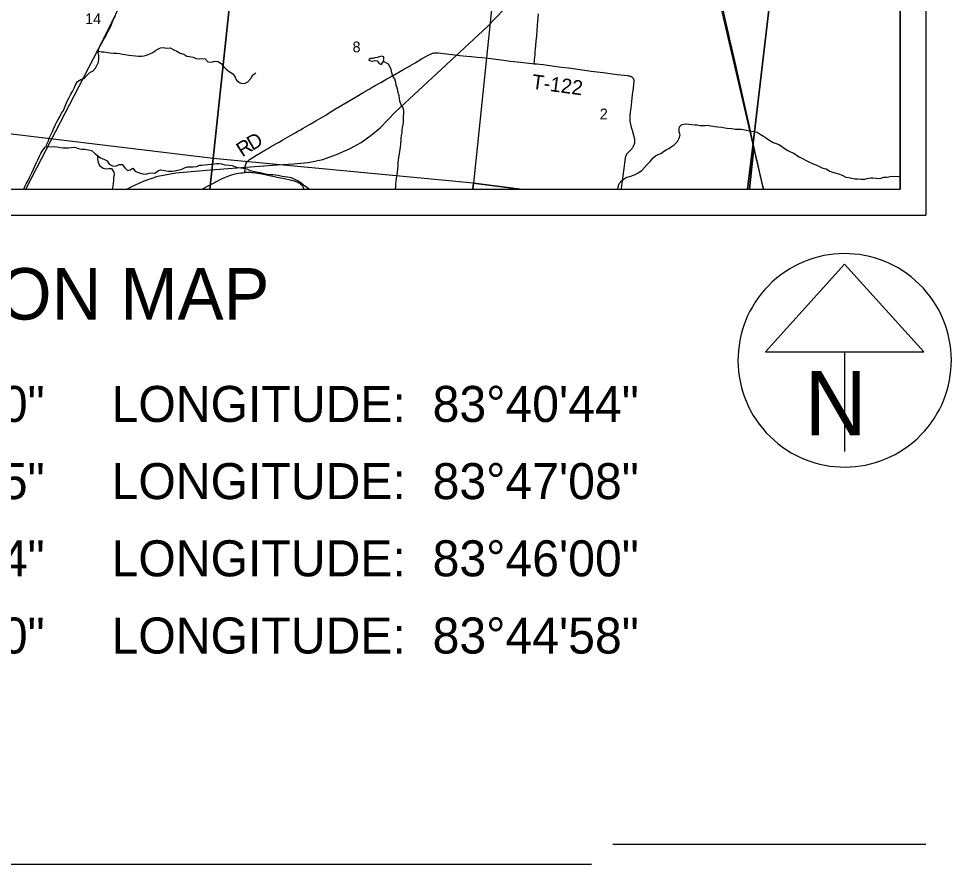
# Model space of a CAD drawing. Extents: x 831 to 1552, y 430 to 870.
# Drawn here: x 1013.2 to 1085.8, y 598.5 to 664.2 of the extents above; entities that cross this region are included whole.
import ezdxf

# ---------------------------------------------------------------- set-up
doc = ezdxf.new("R2010")
doc.units = 0
for name, color, linetype in [('GM_X_Corporation', 7, 'Continuous'), ('GM_X_Minor_Lake', 7, 'Continuous'), ('GM_X_Minor_River', 7, 'Continuous'), ('GM_X_Rail_Line', 7, 'Continuous'), ('GM_X_Section_Text', 7, 'Continuous'), ('GM_X_State_Route', 7, 'Continuous'), ('GM_X_Township_Road', 7, 'Continuous'), ('GM_X_Township_Road_Text', 7, 'Continuous'), ('SH_Data', 7, 'Continuous'), ('SH_Text', 7, 'Continuous')]:
    doc.layers.add(name, color=color, linetype=linetype)

msp = doc.modelspace()

# ---------------------------------------------------------------- linework, layer by layer
at = {"layer": 'GM_X_Corporation'}
msp.add_lwpolyline([(957.479, 781.045), (956.56, 771.006), (955.451, 760.717), (953.653, 740.871), (952.689, 730.885), (949.971, 703.401), (947.763, 681.071), (945.766, 658.183), (945.766, 650.938), (1069.909, 650.938), (1070.34, 654.531), (1072.813, 675.454), (1078.126, 715.958), (1081.227, 740.59), (1081.766, 744.853), (1081.766, 786.938)], dxfattribs=at)
for points in [[(1069.909, 650.938), (1081.766, 650.938), (1081.766, 744.853), (1081.227, 740.59), (1078.126, 715.958), (1072.813, 675.454), (1070.34, 654.531)], [(1030.47, 673.244), (1028.346, 653.321), (1007.707, 655.818), (1009.676, 675.38)], [(1030.47, 673.244), (1050.619, 670.912), (1048.583, 651.419), (1028.346, 653.321)], [(1052.227, 650.938), (1070.052, 650.938), (1070.404, 654.192), (1066.955, 668.986), (1050.619, 670.912), (1048.583, 651.419)], [(1007.28, 650.938), (1028.103, 650.938), (1028.346, 653.321), (1007.707, 655.818)], [(1070.052, 650.938), (1071.14, 650.938), (1070.404, 654.192)], [(1028.103, 650.938), (1048.532, 650.938), (1048.583, 651.419), (1028.346, 653.321)], [(1048.532, 650.938), (1052.227, 650.938), (1048.583, 651.419)]]:
    msp.add_lwpolyline(points, close=True, dxfattribs=at)
at = {"layer": 'GM_X_Minor_Lake'}
for points in [[(1040.485, 661.031), (1040.429, 660.991), (1040.58, 660.92), (1040.77, 660.895), (1040.945, 660.946), (1041.097, 660.913), (1041.246, 660.721), (1041.411, 660.628), (1041.597, 660.868)], [(1041.597, 660.868), (1041.615, 661.05), (1041.617, 661.225), (1041.436, 661.273), (1041.268, 661.222), (1041.093, 661.179), (1040.925, 661.159), (1040.765, 661.115), (1040.583, 661.103), (1040.485, 661.031)]]:
    msp.add_lwpolyline(points, dxfattribs=at)
at = {"layer": 'GM_X_Minor_River'}
for points in [[(1015.364, 654.238), (1015.408, 654.452), (1015.533, 654.716), (1015.604, 654.921), (1015.737, 655.162), (1015.847, 655.442), (1015.95, 655.698), (1016.067, 655.932), (1016.161, 656.136), (1016.293, 656.355), (1016.418, 656.558), (1016.566, 656.852), (1016.706, 657.056), (1016.792, 657.275), (1016.887, 657.539), (1016.989, 657.781), (1017.145, 658.075), (1017.262, 658.279), (1017.426, 658.588), (1017.535, 658.792), (1017.645, 659.048), (1017.808, 659.312), (1018.069, 659.483), (1018.313, 659.541), (1018.552, 659.811), (1018.798, 660.051), (1018.989, 660.116), (1019.19, 660.357), (1019.338, 660.621), (1019.432, 660.817), (1019.466, 661.075), (1019.447, 661.341), (1019.397, 661.569), (1019.454, 661.857), (1019.533, 662.054), (1019.681, 662.295), (1019.798, 662.521), (1019.945, 662.747), (1020.063, 662.981), (1020.188, 663.238), (1020.305, 663.471), (1020.446, 663.758), (1020.532, 663.962), (1020.611, 664.159), (1020.752, 664.43)], [(1019.418, 661.674), (1019.671, 661.634), (1019.876, 661.616), (1020.164, 661.567), (1020.369, 661.541), (1020.604, 661.53), (1020.854, 661.527), (1021.074, 661.493), (1021.309, 661.452), (1021.513, 661.404), (1021.786, 661.355), (1022.059, 661.336), (1022.309, 661.302), (1022.544, 661.276), (1022.757, 661.281), (1022.985, 661.3), (1023.176, 661.374), (1023.42, 661.469), (1023.665, 661.58), (1023.856, 661.714), (1024.055, 661.817), (1024.247, 661.929), (1024.46, 661.971), (1024.732, 661.899), (1024.999, 661.941), (1025.3, 661.77), (1025.526, 661.668), (1025.775, 661.52), (1026.07, 661.448), (1026.31, 661.285), (1026.507, 661.252), (1026.803, 661.195), (1027.006, 661.101), (1027.249, 661.082), (1027.515, 661.094), (1027.727, 661.076), (1027.944, 660.837), (1028.202, 660.826), (1028.469, 660.906), (1028.734, 660.872), (1028.998, 660.686), (1029.154, 660.486), (1029.386, 660.248), (1029.672, 660.046), (1029.875, 659.899), (1030.053, 659.646), (1030.164, 659.432), (1030.389, 659.231), (1030.586, 659.16), (1030.836, 659.179), (1031.051, 659.298), (1031.267, 659.546), (1031.423, 659.825), (1031.676, 659.988)], [(1042.533, 650.938), (1042.544, 651.132), (1042.555, 651.337), (1042.58, 651.541), (1042.614, 651.754), (1042.64, 651.974), (1042.674, 652.231), (1042.708, 652.527), (1042.727, 652.762), (1042.745, 652.982), (1042.763, 653.187), (1042.79, 653.438), (1042.831, 653.68), (1042.872, 653.892), (1042.907, 654.196), (1042.949, 654.491), (1042.96, 654.727), (1042.97, 654.924), (1042.996, 655.129), (1043.037, 655.356), (1043.055, 655.546), (1043.081, 655.743), (1043.114, 655.963), (1043.14, 656.167), (1043.158, 656.41), (1043.161, 656.6), (1043.172, 656.82), (1043.175, 657.071), (1043.095, 657.315), (1042.969, 657.507), (1042.874, 657.781), (1042.832, 658.002), (1042.804, 658.193), (1042.74, 658.459), (1042.675, 658.734), (1042.588, 659.031), (1042.561, 659.229), (1042.466, 659.527), (1042.332, 659.726), (1042.245, 660.001), (1042.18, 660.245), (1042.115, 660.436), (1041.974, 660.673), (1041.597, 660.868)], [(1059.81, 650.938), (1059.84, 651.126), (1059.919, 651.39), (1060.128, 651.623), (1060.419, 651.816), (1060.633, 651.904), (1060.824, 651.962), (1061.175, 652.094), (1061.412, 652.227), (1061.68, 652.405), (1061.904, 652.63), (1062.097, 652.855), (1062.328, 653.11), (1062.567, 653.395), (1062.759, 653.544), (1062.966, 653.633), (1063.157, 653.728), (1063.364, 653.885), (1063.571, 653.996), (1063.777, 654.099), (1063.969, 654.233), (1064.206, 654.382), (1064.453, 654.659), (1064.586, 654.908), (1064.673, 655.173), (1064.6, 655.402), (1064.588, 655.592), (1064.606, 655.781), (1064.806, 655.984), (1065.11, 656.025), (1065.376, 656.006), (1065.573, 655.965), (1065.793, 655.947), (1065.99, 655.944), (1066.217, 655.902), (1066.407, 655.885), (1066.597, 655.897), (1066.802, 655.909), (1067.06, 655.875), (1067.37, 655.818), (1067.597, 655.784), (1067.908, 655.757), (1068.135, 655.715), (1068.325, 655.69), (1068.689, 655.654), (1068.954, 655.62), (1069.159, 655.61), (1069.432, 655.606), (1069.697, 655.557), (1069.962, 655.5), (1070.159, 655.459), (1070.424, 655.44), (1070.651, 655.368), (1070.877, 655.228), (1071.133, 655.065), (1071.366, 654.902), (1071.629, 654.724), (1071.9, 654.568), (1072.119, 654.489), (1072.331, 654.41), (1072.541, 654.293), (1072.759, 654.138), (1073.045, 653.952), (1073.294, 653.835), (1073.513, 653.74), (1073.708, 653.586), (1073.927, 653.469), (1074.183, 653.344), (1074.469, 653.165), (1074.725, 653.04), (1074.967, 652.93), (1075.261, 652.82), (1075.495, 652.718), (1075.759, 652.585), (1076.016, 652.521), (1076.31, 652.357), (1076.521, 652.263), (1076.786, 652.183), (1076.99, 652.135), (1077.255, 652.032), (1077.556, 651.884)], [(1013.62, 650.938), (1013.713, 651.148), (1013.815, 651.359), (1013.955, 651.631), (1014.073, 651.865), (1014.182, 652.068), (1014.268, 652.272), (1014.37, 652.491), (1014.48, 652.748), (1014.582, 652.959), (1014.707, 653.216), (1014.856, 653.518), (1014.942, 653.714), (1015.098, 653.985), (1015.306, 654.233), (1015.549, 654.253), (1015.762, 654.227), (1016.035, 654.261), (1016.225, 654.244), (1016.475, 654.195), (1016.679, 654.154), (1016.869, 654.159)], [(1016.869, 654.159), (1017.112, 654.171), (1017.318, 654.183), (1017.591, 654.202), (1017.863, 654.1), (1018.121, 654.058), (1018.356, 654.063), (1018.644, 654.006), (1018.894, 653.949), (1019.126, 653.748), (1019.351, 653.555), (1019.599, 653.377), (1019.841, 653.267), (1020.105, 653.158), (1020.261, 652.889), (1020.525, 652.772), (1020.79, 652.723), (1021.042, 652.856), (1021.285, 652.86), (1021.479, 652.599), (1021.696, 652.391), (1021.902, 652.457), (1022.093, 652.568), (1022.288, 652.345), (1022.59, 652.22), (1022.869, 652.14), (1023.097, 652.114), (1023.379, 652.194), (1023.637, 652.205), (1023.827, 652.195), (1024.088, 652.397), (1024.279, 652.447), (1024.574, 652.398), (1024.839, 652.341), (1025.158, 652.344), (1025.348, 652.364), (1025.592, 652.429), (1025.866, 652.486), (1026.126, 652.597), (1026.362, 652.677), (1026.59, 652.689), (1026.803, 652.671), (1027.084, 652.72), (1027.275, 652.801), (1027.481, 652.814), (1027.671, 652.834), (1027.945, 652.876), (1028.226, 652.895), (1028.416, 652.907), (1028.606, 652.935), (1028.796, 652.94), (1029.001, 652.914), (1029.265, 652.85), (1029.599, 652.8), (1029.819, 652.782), (1030.098, 652.671), (1030.303, 652.631), (1030.5, 652.605), (1030.689, 652.58), (1030.962, 652.523), (1031.226, 652.405), (1031.423, 652.357), (1031.703, 652.3), (1031.998, 652.243), (1032.301, 652.163), (1032.558, 652.121), (1032.808, 652.095), (1032.998, 652.077), (1033.195, 652.052), (1033.407, 652.026), (1033.71, 651.968), (1033.93, 651.92), (1034.134, 651.902), (1034.414, 651.845), (1034.671, 651.727), (1034.965, 651.587), (1035.161, 651.462), (1035.363, 651.285), (1035.634, 651.091), (1035.852, 650.959), (1035.872, 650.938)], [(1019.344, 653.562), (1019.348, 653.305), (1019.405, 653.038), (1019.515, 652.793), (1019.793, 652.577), (1019.997, 652.521), (1020.233, 652.563), (1020.438, 652.545), (1020.624, 652.269), (1020.659, 652.071), (1020.61, 651.836), (1020.6, 651.639), (1020.573, 651.389), (1020.548, 651.191), (1020.507, 650.979), (1020.502, 650.938)], [(1077.556, 651.884), (1077.746, 651.858), (1078.003, 651.802), (1078.245, 651.76), (1078.488, 651.742), (1078.746, 651.723), (1079.019, 651.712), (1079.21, 651.77), (1079.461, 651.82), (1079.651, 651.825), (1079.901, 651.791), (1080.091, 651.766), (1080.296, 651.808), (1080.51, 651.874), (1080.73, 651.886), (1081.004, 651.935), (1081.194, 651.948), (1081.665, 651.941), (1081.766, 651.917)]]:
    msp.add_lwpolyline(points, dxfattribs=at)
at = {"layer": 'GM_X_Rail_Line'}
for points in [[(1013.791, 650.938), (1014.28, 651.895), (1019.767, 662.513), (1021.761, 666.57)], [(1021.639, 650.938), (1022.016, 651.166), (1022.93, 651.563), (1024.049, 651.948), (1025.46, 652.211), (1028.142, 652.462), (1031.589, 652.721), (1033.328, 652.847), (1034.588, 652.912), (1035.748, 653.032), (1036.888, 653.266), (1037.951, 653.654), (1038.992, 654.116), (1039.861, 654.582), (1040.64, 655.139), (1041.328, 655.716), (1042.519, 656.956), (1049.69, 663.597), (1050.96, 664.907)]]:
    msp.add_lwpolyline(points, dxfattribs=at)
at = {"layer": 'GM_X_State_Route'}
for points in [[(1070.344, 654.52), (1070.319, 654.632), (1069.998, 656.076), (1069.752, 657.218), (1068.986, 660.587), (1068.675, 661.931), (1068.551, 662.476), (1068.414, 663.082), (1067.971, 664.982), (1067.809, 665.697), (1067.657, 666.364), (1067.497, 667.054), (1067.391, 667.527), (1067.214, 668.315), (1067.059, 668.99)], [(1071.161, 650.938), (1071.122, 651.106), (1070.872, 652.221), (1070.607, 653.372), (1070.508, 653.796), (1070.344, 654.52)]]:
    msp.add_lwpolyline(points, dxfattribs=at)
at = {"layer": 'GM_X_Township_Road'}
for points in [[(1053.307, 660.701), (1053.309, 660.718), (1053.326, 660.881), (1053.341, 661.022), (1053.358, 661.17), (1053.382, 661.38), (1053.39, 661.479), (1053.402, 661.652), (1053.417, 661.863), (1053.439, 662.098), (1053.476, 662.481), (1053.511, 662.877), (1053.576, 663.694), (1053.649, 664.586)], [(1030.825, 652.24), (1030.826, 652.538), (1030.83, 652.626), (1030.842, 652.726), (1030.86, 652.813), (1030.886, 652.898), (1030.923, 652.98), (1030.972, 653.054), (1031.03, 653.122), (1031.093, 653.184), (1031.171, 653.249), (1031.295, 653.334), (1031.583, 653.508), (1032.432, 653.999), (1032.657, 654.132), (1032.817, 654.227), (1033.279, 654.496), (1033.474, 654.605), (1033.775, 654.778), (1034.301, 655.084), (1034.73, 655.335), (1034.793, 655.373), (1034.944, 655.458), (1035.129, 655.559), (1035.345, 655.681), (1035.883, 655.992), (1036.322, 656.25), (1036.686, 656.465), (1037.102, 656.712), (1037.536, 656.979), (1037.873, 657.19), (1038.343, 657.47), (1038.859, 657.768), (1039.682, 658.256), (1040.076, 658.493), (1040.474, 658.725), (1040.645, 658.824), (1040.947, 658.995), (1041.389, 659.248), (1041.787, 659.477), (1042.293, 659.769), (1043.102, 660.232), (1043.61, 660.519), (1043.696, 660.569), (1044.052, 660.773), (1044.556, 661.067), (1044.9, 661.266), (1045.064, 661.357), (1045.12, 661.383), (1045.196, 661.427), (1045.3, 661.473), (1045.408, 661.508), (1045.457, 661.519), (1045.57, 661.536), (1045.683, 661.541), (1045.834, 661.534), (1046.045, 661.511), (1047.152, 661.378), (1047.522, 661.339), (1047.794, 661.315), (1048.066, 661.292), (1048.413, 661.265), (1048.883, 661.219), (1049.254, 661.179), (1049.723, 661.123), (1050.758, 660.988), (1051.46, 660.903), (1052.237, 660.811), (1052.895, 660.737), (1053.146, 660.715), (1053.307, 660.701)], [(1053.307, 660.701), (1053.515, 660.683), (1053.725, 660.662), (1054.048, 660.63), (1054.34, 660.595), (1055.447, 660.44), (1055.99, 660.369), (1056.704, 660.272), (1057.75, 660.127), (1058.674, 660.009), (1059.032, 659.962), (1059.759, 659.869), (1060.568, 659.77), (1060.643, 659.759), (1060.7, 659.749), (1060.744, 659.739), (1060.778, 659.73), (1060.812, 659.719), (1060.845, 659.706), (1060.879, 659.689), (1060.907, 659.672), (1060.934, 659.652), (1060.953, 659.635), (1060.977, 659.609), (1060.997, 659.584), (1061.011, 659.562), (1061.028, 659.528), (1061.038, 659.497), (1061.047, 659.468), (1061.054, 659.439), (1061.059, 659.405), (1061.06, 659.367), (1061.061, 659.33), (1061.058, 659.282), (1061.036, 659.073), (1061.001, 658.802), (1060.934, 658.272), (1060.819, 657.247), (1060.783, 656.938), (1060.753, 656.641), (1060.747, 656.549), (1060.74, 656.454), (1060.74, 656.341), (1060.75, 656.228), (1060.77, 656.116), (1060.861, 655.754), (1060.923, 655.526), (1061.007, 655.24), (1061.073, 655.014), (1061.105, 654.87), (1061.109, 654.845), (1061.114, 654.821), (1061.12, 654.766), (1061.123, 654.729), (1061.125, 654.685), (1061.124, 654.645), (1061.122, 654.608), (1061.118, 654.571), (1061.113, 654.532), (1061.106, 654.501), (1061.095, 654.462), (1061.087, 654.437), (1061.078, 654.415), (1061.058, 654.369), (1061.039, 654.332), (1061.026, 654.306), (1061.012, 654.279), (1060.976, 654.218), (1060.947, 654.17), (1060.911, 654.111), (1060.88, 654.063), (1060.861, 654.036), (1060.836, 654.004), (1060.794, 653.959), (1060.757, 653.921), (1060.601, 653.774), (1060.576, 653.748), (1060.541, 653.709), (1060.522, 653.684), (1060.503, 653.658), (1060.488, 653.635), (1060.47, 653.602), (1060.455, 653.57), (1060.439, 653.533), (1060.424, 653.492), (1060.412, 653.448), (1060.401, 653.402), (1060.389, 653.35), (1060.333, 652.957), (1060.276, 652.563), (1060.252, 652.375), (1060.203, 651.993), (1060.127, 651.406), (1060.078, 650.999), (1060.071, 650.938)], [(1027.49, 650.938), (1027.853, 651.143), (1028.17, 651.315), (1028.719, 651.607), (1028.886, 651.69), (1029.307, 651.878), (1029.574, 651.981), (1029.798, 652.058), (1029.978, 652.111), (1030.16, 652.154), (1030.344, 652.188), (1030.517, 652.212), (1030.653, 652.225), (1030.825, 652.24)], [(1035.412, 650.938), (1035.406, 650.958), (1035.396, 650.99), (1035.37, 651.058), (1035.337, 651.122), (1035.296, 651.182), (1035.265, 651.221), (1035.232, 651.254), (1035.191, 651.291), (1035.117, 651.352), (1035.081, 651.378), (1034.998, 651.431), (1034.964, 651.451), (1034.924, 651.473), (1034.872, 651.496), (1034.809, 651.52), (1034.742, 651.542), (1034.658, 651.566), (1034.569, 651.589), (1034.453, 651.616), (1034.355, 651.638), (1034.232, 651.664), (1034.004, 651.712), (1033.316, 651.86), (1032.98, 651.931), (1032.692, 651.994), (1032.386, 652.058), (1032.144, 652.107), (1031.945, 652.144), (1031.786, 652.171), (1031.65, 652.193), (1031.47, 652.215), (1031.347, 652.227), (1031.256, 652.234), (1031.133, 652.241), (1031.018, 652.244), (1030.931, 652.242), (1030.825, 652.24)]]:
    msp.add_lwpolyline(points, dxfattribs=at)
at = {"layer": 'SH_Data'}
for p, q in [((1083.766, 788.938), (1083.766, 648.938)), ((1081.766, 786.938), (1081.766, 650.938)), ((945.766, 650.938), (1081.766, 650.938)), ((943.766, 648.938), (1083.766, 648.938)), ((1077.457, 645.119), (1071.305, 638.294)), ((1083.608, 638.294), (1077.457, 645.119)), ((1071.305, 638.294), (1083.608, 638.294)), ((1077.457, 638.294), (1077.457, 630.559)), ((1077.457, 637.644), (1077.457, 637.644)), ((1077.457, 637.644), (1077.457, 637.644)), ((1059.42, 600.044), (1083.766, 600.044)), ((1057.766, 598.471), (993.64, 598.471))]:
    msp.add_line(p, q, dxfattribs=at)
msp.add_arc((1077.457, 637.644), 8.296, 129.77984, 129.76332, dxfattribs=at)

# ---------------------------------------------------------------- texts
at = {"layer": 'GM_X_Section_Text'}
for s, height, p in [('14', 0.8371, (1018.396, 663.775)), ('8', 0.837, (1039.188, 661.585)), ('2', 0.837, (1058.413, 656.375))]:
    msp.add_text(s, height=height, rotation=0.00001, dxfattribs=at).set_placement(p)
at = {"layer": 'GM_X_Township_Road_Text'}
for s, height, rotation, p in [('T-122', 1.1364, 352.38743, (1053.076, 658.762)), ('D', 1.136, 30.55456, (1031.391, 653.91)), ('R', 1.136, 32.97559, (1030.619, 653.409))]:
    msp.add_text(s, height=height, rotation=rotation, dxfattribs=at).set_placement(p)
at = {"layer": 'SH_Data'}
msp.add_text('N', height=5, dxfattribs=at).set_placement((1074.35, 631.817))
at = {"layer": 'SH_Text'}
for s, height, p in [('LOCATION MAP', 4, (992.305, 640.813)), ('CHP-245-1302     LATITUDE:  40°12\'50"     LONGITUDE:  83°40\'44"', 2.8, (947.816, 632.855)), ('CHP-296-0021     LATITUDE:  40°09\'25"     LONGITUDE:  83°47\'08"', 2.8, (947.816, 626.855)), ('CHP-296-0122     LATITUDE:  40°09\'24"     LONGITUDE:  83°46\'00"', 2.8, (947.816, 620.855)), ('CHP-296-0212     LATITUDE:  40°09\'20"     LONGITUDE:  83°44\'58"', 2.8, (947.816, 614.855))]:
    msp.add_text(s, height=height, dxfattribs=at).set_placement(p)

doc.saveas('drawing.dxf')
